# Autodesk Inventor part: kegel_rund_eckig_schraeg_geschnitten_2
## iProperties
Created: 2005-09
Part Number: kegel_rund_eckig_schraeg_geschnitten_2
Cost Center: 0,1 kg
Document SubType Name: Blech
Designer: Administrator
Authority: 65068,21 mm^3
SaveDate: 2005-09-15
SaveTime: 10:05
TotalMass: 0,1 kg
TotalVolume: 65068,21 mm^3
SM_Thickness: 1 mm
SM_Style: Standard
SM_Extents: 360,857 mm x 272,706 mm
Author: Administrator
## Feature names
1. Runde Anordnung1 [Circular Pattern]
2. Trennen2
3. Trennen3
4. Trennen4
5. Trennen5
6. Trennen6
7. Trennen7
8. Trennen8
9. Trennen9
10. Trennen10
11. Trennen11
12. Trennen12
13. Extrusion12
14. Spiegeln2 [Mirror]
15. Grobblech1
16. Grobblech2
17. Biegung1
18. Grobblech3
19. Biegung2
20. Grobblech4
21. Biegung3
22. Grobblech5
23. Biegung4
24. Grobblech6
25. Biegung5
26. Grobblech7
27. Biegung6
28. Grobblech8
29. Biegung7
30. Grobblech9
31. Biegung8
32. Grobblech10
33. Biegung9
34. Grobblech11
35. Biegung10
36. ExtrusionAbwicklung1
